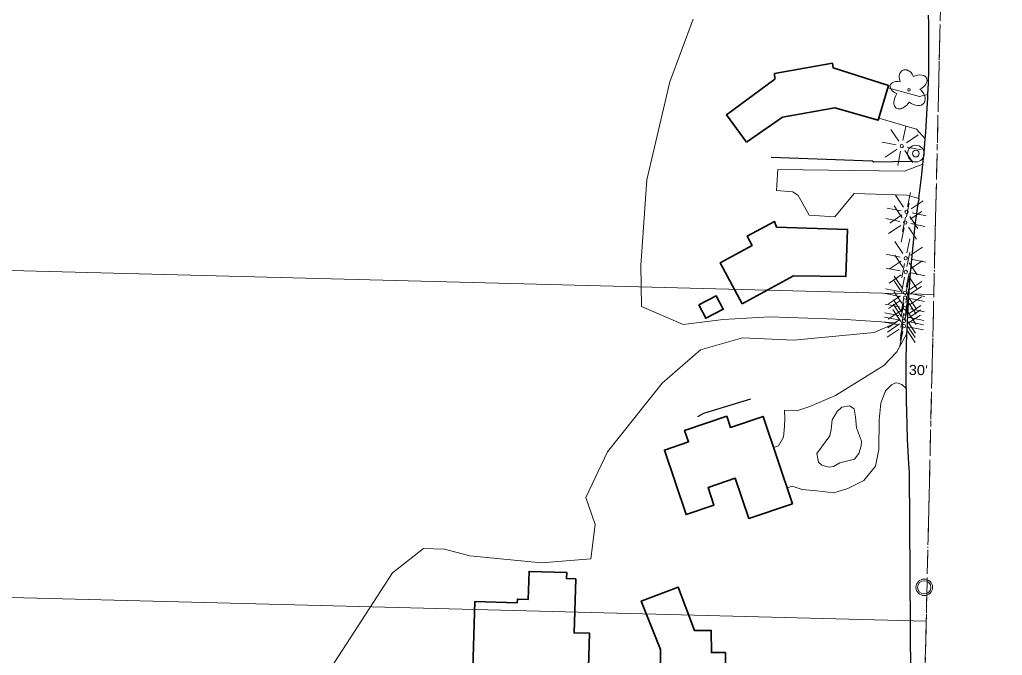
# Model space of a CAD drawing. Extents: x -861682 to -858969, y -1797841 to -1795153.
# Drawn here: x -859566 to -858974, y -1797184 to -1796801 of the extents above; entities that cross this region are included whole.
import ezdxf

# ---------------------------------------------------------------- set-up
doc = ezdxf.new("R2010")
doc.units = 0
doc.header["$LTSCALE"] = 2.4
doc.linetypes.add('DOT_DASHED', pattern=[7.7, 5, -1.2, 0.3, -1.2])
doc.linetypes.add('LONG_DASH_SHORT_DASH', pattern=[9.9, 6, -1.2, 1.5, -1.2])
for name, color, linetype, lineweight in [('10', 7, 'Continuous', 25), ('11', 7, 'Continuous', 13), ('12', 7, 'Continuous', 35), ('14', 7, 'Continuous', 25), ('17', 7, 'Continuous', 13), ('18', 7, 'Continuous', 13), ('30', 7, 'Continuous', 13), ('31', 7, 'Continuous', 13), ('32', 7, 'LONG_DASH_SHORT_DASH', 13), ('36', 7, 'Continuous', 13), ('61', 7, 'Continuous', 13)]:
    doc.layers.add(name, color=color, linetype=linetype, lineweight=lineweight)
doc.layers.add('43', color=7, linetype='Continuous')

msp = doc.modelspace()

# ---------------------------------------------------------------- linework, layer by layer
at = {"layer": '10'}
for p, q in [((-859024.72, -1796908.735), (-859024.961, -1796910.654)), ((-859030.522, -1797073.318), (-859029.495, -1797214.848))]:
    msp.add_line(p, q, dxfattribs=at)
for points in [[(-859019.18, -1796846.215), (-859018.913, -1796839.312), (-859018.708, -1796831.601), (-859018.601, -1796824.99), (-859018.565, -1796820.582), (-859018.557, -1796817.276), (-859018.56, -1796815.072), (-859018.588, -1796810.664), (-859018.695, -1796803.495), (-859018.813, -1796798.497)], [(-859020.84, -1796872.822), (-859020.518, -1796869.02), (-859019.773, -1796858.026), (-859019.254, -1796848.121), (-859019.18, -1796846.215)], [(-859022.275, -1796888.192), (-859021.542, -1796881.099), (-859020.84, -1796872.822)], [(-859024.72, -1796908.735), (-859022.903, -1796894.252), (-859022.275, -1796888.192)], [(-859031.785, -1796989.999), (-859031.739, -1796988.57), (-859031.299, -1796978.662), (-859030.667, -1796967.66), (-859029.621, -1796953.373), (-859028.537, -1796941.3), (-859026.767, -1796924.865), (-859024.961, -1796910.654)], [(-859032.318, -1797023.072), (-859032.326, -1797021.623), (-859032.329, -1797019.419), (-859032.322, -1797016.113), (-859032.292, -1797011.705), (-859032.202, -1797005.094), (-859032.028, -1796997.382), (-859031.785, -1796989.999)], [(-859032.318, -1797023.072), (-859032.31, -1797024.929), (-859032.253, -1797030.439), (-859032.135, -1797037.049), (-859031.929, -1797044.761), (-859031.604, -1797053.571), (-859030.842, -1797068.328), (-859030.522, -1797073.318)]]:
    msp.add_lwpolyline(points, dxfattribs=at)
at = {"layer": '11'}
for points in [[(-859043.287, -1796842.277), (-859024.301, -1796847.432), (-859019.18, -1796846.215)], [(-859048.691, -1796860.39), (-859026.121, -1796867.138), (-859020.84, -1796872.822)], [(-859024.72, -1796908.735), (-859031.775, -1796906.68), (-859063.615, -1796905.802), (-859075.124, -1796919.876), (-859090.539, -1796918.735), (-859097.27, -1796906.978), (-859100.381, -1796904.715), (-859110.27, -1796903.883), (-859109.563, -1796891.373), (-859033.347, -1796892.373), (-859022.275, -1796888.192)], [(-859112.048, -1797058.472), (-859109.015, -1797057.494), (-859106.144, -1797052.254), (-859105.419, -1797045.672), (-859105.324, -1797041.026), (-859105.523, -1797035.979), (-859097.509, -1797036.218), (-859090.292, -1797033.891), (-859074.714, -1797027.204), (-859045.723, -1797009.172), (-859037.895, -1797001.052), (-859031.785, -1796989.999)], [(-859103.872, -1797082.861), (-859100.926, -1797081.857), (-859094.737, -1797083.799), (-859086.084, -1797084.524), (-859075.743, -1797085.798), (-859067.271, -1797083.262), (-859057.704, -1797078.466), (-859050.82, -1797069.651), (-859048.803, -1797059.675), (-859048.531, -1797041.817), (-859047.536, -1797031.874), (-859044.623, -1797024.406), (-859041.126, -1797020.926), (-859038.753, -1797019.638), (-859037.007, -1797019.746), (-859034.862, -1797020.611), (-859032.318, -1797023.072)]]:
    msp.add_lwpolyline(points, dxfattribs=at)
msp.add_lwpolyline([(-859072.261, -1797067.829), (-859063.427, -1797065.633), (-859060.659, -1797062.076), (-859059.386, -1797057.438), (-859059.245, -1797054.643), (-859062.159, -1797046.594), (-859062.835, -1797039.989), (-859063.53, -1797035.23), (-859066.415, -1797033.459), (-859070.928, -1797034.296), (-859073.76, -1797036.83), (-859076.88, -1797041.959), (-859077.393, -1797047.694), (-859078.205, -1797051.563), (-859085.958, -1797062.078), (-859085.003, -1797067.266), (-859082.946, -1797069.05), (-859078.69, -1797070.3), (-859076.084, -1797069.887)], close=True, dxfattribs=at)
at = {"layer": '12'}
for points in [[(-859128.246, -1796874.898), (-859106.732, -1796859.768), (-859075.22, -1796854.136), (-859049.07, -1796861.659), (-859042.826, -1796840.732), (-859076.192, -1796830.117), (-859076.672, -1796827.431), (-859111.402, -1796833.638), (-859111.375, -1796837.026), (-859140.394, -1796858.425)], [(-859130.951, -1796972.06), (-859099.968, -1796955.298), (-859068.521, -1796955.75), (-859067.538, -1796927.473), (-859110.269, -1796925.987), (-859111.495, -1796922.579), (-859127.981, -1796931.496), (-859124.971, -1796937.061), (-859144.243, -1796947.485)], [(-859156.954, -1796972.765), (-859146.489, -1796967.357), (-859142.332, -1796975.402), (-859152.797, -1796980.81)], [(-859100.701, -1797092.323), (-859118.303, -1797039.813), (-859138.005, -1797046.417), (-859140.248, -1797039.725), (-859165.531, -1797048.199), (-859163.182, -1797055.207), (-859177.651, -1797060.057), (-859164.646, -1797098.855), (-859147.873, -1797093.233), (-859151.466, -1797082.514), (-859135.061, -1797077.015), (-859126.977, -1797101.131)], [(-859293.028, -1797191.733), (-859291.802, -1797151.153), (-859266.164, -1797151.928), (-859266.098, -1797149.742), (-859259.591, -1797149.938), (-859259.084, -1797133.096), (-859236.439, -1797133.778), (-859236.547, -1797137.368), (-859230.999, -1797137.535), (-859231.977, -1797170.014), (-859222.695, -1797170.294), (-859223.313, -1797190.787), (-859227.899, -1797190.649), (-859228.677, -1797216.497), (-859258.24, -1797215.607), (-859257.554, -1797192.801)], [(-859188.067, -1797239.176), (-859188.171, -1797214.698), (-859212.563, -1797214.801), (-859212.607, -1797204.4), (-859191.694, -1797204.312), (-859191.671, -1797209.768), (-859179.866, -1797209.719), (-859179.991, -1797179.954), (-859191.675, -1797150.887), (-859169.429, -1797142.508), (-859159.61, -1797168.611), (-859149.486, -1797168.569), (-859149.43, -1797181.911), (-859141.05, -1797181.876), (-859140.905, -1797216.333), (-859153.003, -1797216.384), (-859153.037, -1797208.389), (-859165.952, -1797208.444), (-859165.098, -1797238.609)]]:
    msp.add_lwpolyline(points, close=True, dxfattribs=at)
at = {"layer": '14'}
for points in [[(-859028.47, -1796886.438), (-859051.691, -1796886.855), (-859052.743, -1796886.344), (-859113.392, -1796884.009)], [(-859157.508, -1797039.963), (-859154.038, -1797037.947), (-859125.659, -1797029.308)]]:
    msp.add_lwpolyline(points, dxfattribs=at)
at = {"layer": '17'}
for p, q in [((-859036.757, -1796874.325), (-859041.547, -1796867.197)), ((-859034.297, -1796873.865), (-859032.571, -1796865.465)), ((-859032.097, -1796875.265), (-859025.001, -1796870.525)), ((-859038.257, -1796876.525), (-859046.719, -1796874.851)), ((-859037.717, -1796879.025), (-859044.943, -1796883.881)), ((-859031.657, -1796877.785), (-859023.177, -1796879.509)), ((-859037.337, -1796888.985), (-859035.657, -1796880.385)), ((-859032.997, -1796879.925), (-859028.197, -1796887.139)), ((-859033.846, -1796913.95), (-859038.636, -1796906.822)), ((-859031.386, -1796913.49), (-859029.66, -1796905.09)), ((-859035.346, -1796916.15), (-859043.808, -1796914.476)), ((-859034.622, -1796920.338), (-859039.412, -1796913.21)), ((-859032.162, -1796919.878), (-859030.436, -1796911.478)), ((-859029.186, -1796914.89), (-859022.09, -1796910.15)), ((-859034.806, -1796918.65), (-859042.032, -1796923.506)), ((-859034.426, -1796928.61), (-859032.746, -1796920.01)), ((-859030.086, -1796919.55), (-859025.286, -1796926.764)), ((-859029.962, -1796921.278), (-859022.866, -1796916.538)), ((-859028.746, -1796917.41), (-859020.266, -1796919.134)), ((-859036.122, -1796922.538), (-859044.584, -1796920.864)), ((-859035.582, -1796925.038), (-859042.808, -1796929.894)), ((-859035.202, -1796934.998), (-859033.522, -1796926.398)), ((-859030.862, -1796925.938), (-859026.062, -1796933.152)), ((-859029.522, -1796923.798), (-859021.042, -1796925.522)), ((-859034.291, -1796941.803), (-859039.081, -1796934.675)), ((-859031.831, -1796941.343), (-859030.105, -1796932.943)), ((-859029.631, -1796942.743), (-859022.535, -1796938.003)), ((-859035.791, -1796944.003), (-859044.253, -1796942.329)), ((-859034.353, -1796950.052), (-859039.143, -1796942.924)), ((-859031.893, -1796949.592), (-859030.167, -1796941.192)), ((-859035.251, -1796946.503), (-859042.477, -1796951.359)), ((-859034.871, -1796956.463), (-859033.191, -1796947.863)), ((-859030.531, -1796947.403), (-859025.731, -1796954.617)), ((-859029.693, -1796950.992), (-859022.597, -1796946.252)), ((-859029.191, -1796945.263), (-859020.711, -1796946.987)), ((-859035.853, -1796952.252), (-859044.315, -1796950.578)), ((-859035.313, -1796954.752), (-859042.539, -1796959.608)), ((-859034.707, -1796962.52), (-859039.497, -1796955.392)), ((-859032.247, -1796962.06), (-859030.521, -1796953.66)), ((-859030.593, -1796955.652), (-859025.793, -1796962.866)), ((-859029.253, -1796953.512), (-859020.773, -1796955.236)), ((-859034.76, -1796965.448), (-859039.55, -1796958.32)), ((-859034.933, -1796964.712), (-859033.253, -1796956.112)), ((-859032.3, -1796964.988), (-859030.574, -1796956.588)), ((-859030.1, -1796966.388), (-859023.004, -1796961.648)), ((-859030.047, -1796963.46), (-859022.951, -1796958.72)), ((-859036.26, -1796967.648), (-859044.722, -1796965.974)), ((-859036.207, -1796964.72), (-859044.669, -1796963.046)), ((-859035.667, -1796967.22), (-859042.893, -1796972.076)), ((-859034.862, -1796971.75), (-859039.652, -1796964.622)), ((-859032.402, -1796971.29), (-859030.676, -1796962.89)), ((-859029.607, -1796965.98), (-859021.127, -1796967.704)), ((-859036.362, -1796973.95), (-859044.824, -1796972.276)), ((-859035.72, -1796970.148), (-859042.946, -1796975.004)), ((-859035.341, -1796979.527), (-859040.131, -1796972.399)), ((-859035.181, -1796976.924), (-859039.971, -1796969.796)), ((-859035.34, -1796980.108), (-859033.66, -1796971.508)), ((-859035.287, -1796977.18), (-859033.607, -1796968.58)), ((-859033.009, -1796982.181), (-859031.283, -1796973.781)), ((-859032.881, -1796979.067), (-859031.155, -1796970.667)), ((-859032.721, -1796976.464), (-859030.995, -1796968.064)), ((-859031, -1796971.048), (-859026.2, -1796978.262)), ((-859030.947, -1796968.12), (-859026.147, -1796975.334)), ((-859030.521, -1796977.864), (-859023.425, -1796973.124)), ((-859030.202, -1796972.69), (-859023.106, -1796967.95)), ((-859029.66, -1796968.908), (-859021.18, -1796970.632)), ((-859036.681, -1796979.124), (-859045.143, -1796977.45)), ((-859035.822, -1796976.45), (-859043.048, -1796981.306)), ((-859035.469, -1796982.641), (-859040.259, -1796975.513)), ((-859035.442, -1796986.41), (-859033.762, -1796977.81)), ((-859031.102, -1796977.35), (-859026.302, -1796984.564)), ((-859030.809, -1796983.581), (-859023.713, -1796978.841)), ((-859030.681, -1796980.467), (-859023.585, -1796975.727)), ((-859029.762, -1796975.21), (-859021.282, -1796976.934)), ((-859036.969, -1796984.841), (-859045.431, -1796983.167)), ((-859036.841, -1796981.727), (-859045.303, -1796980.053)), ((-859036.301, -1796984.227), (-859043.527, -1796989.083)), ((-859036.141, -1796981.624), (-859043.367, -1796986.48)), ((-859035.921, -1796994.187), (-859034.241, -1796985.587)), ((-859035.761, -1796991.584), (-859034.081, -1796982.984)), ((-859031.581, -1796985.127), (-859026.781, -1796992.341)), ((-859031.421, -1796982.524), (-859026.621, -1796989.738)), ((-859030.241, -1796982.987), (-859021.761, -1796984.711)), ((-859030.081, -1796980.384), (-859021.601, -1796982.108)), ((-859036.429, -1796987.341), (-859043.655, -1796992.197)), ((-859036.049, -1796997.301), (-859034.369, -1796988.701)), ((-859031.709, -1796988.241), (-859026.909, -1796995.455)), ((-859030.369, -1796986.101), (-859021.889, -1796987.825))]:
    msp.add_line(p, q, dxfattribs=at)
msp.add_lwpolyline([(-859030.411, -1796850.791), (-859029.369, -1796851.559), (-859027.963, -1796852.281), (-859026.715, -1796852.687), (-859025.343, -1796852.883), (-859024.325, -1796852.833), (-859023.181, -1796852.543), (-859022.249, -1796851.991), (-859021.509, -1796851.203), (-859021.041, -1796850.245), (-859020.831, -1796849.167), (-859020.935, -1796847.971), (-859021.225, -1796846.799), (-859021.711, -1796845.739), (-859022.433, -1796844.595), (-859023.299, -1796843.675), (-859023.981, -1796843.063), (-859022.799, -1796842.347), (-859021.653, -1796841.399), (-859020.733, -1796840.307), (-859020.211, -1796839.451), (-859019.879, -1796838.637), (-859019.733, -1796837.821), (-859019.773, -1796837.059), (-859019.989, -1796836.379), (-859020.247, -1796835.927), (-859020.667, -1796835.453), (-859021.127, -1796835.099), (-859021.693, -1796834.809), (-859022.929, -1796834.481), (-859024.171, -1796834.447), (-859026.217, -1796834.823), (-859027.877, -1796835.461), (-859028.667, -1796833.883), (-859029.321, -1796833.069), (-859029.733, -1796832.667), (-859030.197, -1796832.267), (-859030.799, -1796831.875), (-859031.803, -1796831.443), (-859032.817, -1796831.273), (-859033.705, -1796831.373), (-859034.505, -1796831.707), (-859035.171, -1796832.193), (-859035.731, -1796832.899), (-859036.081, -1796833.655), (-859036.239, -1796834.093), (-859036.407, -1796834.769), (-859036.459, -1796835.931), (-859036.387, -1796836.829), (-859036.175, -1796837.791), (-859035.891, -1796838.597), (-859037.333, -1796838.365), (-859038.691, -1796838.415), (-859039.849, -1796838.701), (-859040.737, -1796839.199), (-859041.177, -1796839.543), (-859041.611, -1796840.109), (-859041.849, -1796840.643), (-859041.973, -1796841.321), (-859041.771, -1796842.425), (-859041.315, -1796843.237), (-859040.691, -1796843.999), (-859039.913, -1796844.615), (-859039.215, -1796845.039), (-859038.551, -1796845.327), (-859037.823, -1796845.565), (-859038.507, -1796846.777), (-859039.129, -1796848.145), (-859039.525, -1796849.647), (-859039.659, -1796850.981), (-859039.649, -1796852.071), (-859039.315, -1796853.089), (-859038.793, -1796853.935), (-859038.235, -1796854.371), (-859037.849, -1796854.617), (-859037.115, -1796854.841), (-859036.321, -1796854.853), (-859035.551, -1796854.729), (-859034.891, -1796854.517), (-859034.147, -1796854.195), (-859033.071, -1796853.515), (-859032.109, -1796852.729), (-859031.153, -1796851.711), (-859030.407, -1796850.801)], dxfattribs=at)
for centre, radius in [((-859030.591, -1796843.379), 0.773), ((-859034.957, -1796877.225), 1), ((-859032.046, -1796916.85), 1), ((-859032.822, -1796923.238), 1), ((-859032.491, -1796944.703), 1), ((-859032.553, -1796952.952), 1), ((-859032.96, -1796968.348), 1), ((-859032.907, -1796965.42), 1), ((-859033.062, -1796974.65), 1), ((-859033.381, -1796979.824), 1), ((-859033.669, -1796985.541), 1), ((-859033.541, -1796982.427), 1)]:
    msp.add_circle(centre, radius, dxfattribs=at)
at = {"layer": '18'}
msp.add_lwpolyline([(-859385.245, -1797201.598), (-859341.309, -1797133.89), (-859322.661, -1797119.267), (-859309.907, -1797119.639), (-859294.706, -1797123.73), (-859251.594, -1797127.82), (-859221.915, -1797125.507), (-859219.271, -1797104.832), (-859224.872, -1797088.684), (-859211.894, -1797061.126), (-859178.991, -1797019.917), (-859156.053, -1796999.792), (-859130.756, -1796992.589), (-859099.874, -1796994.014), (-859051.539, -1796989.345), (-859038.372, -1796983.529), (-859068.61, -1796981.475), (-859114.201, -1796979.876), (-859142.274, -1796981.46), (-859166.334, -1796984.629), (-859191.529, -1796973.646), (-859191.8, -1796949.095), (-859188.271, -1796897.505), (-859174.444, -1796838.584), (-859160.301, -1796800.902)], dxfattribs=at)
at = {"layer": '30'}
for p, q in [((-859015.656, -1796966.547), (-859737.749, -1796947.769)), ((-859020.232, -1797163.052), (-859830.702, -1797141.975))]:
    msp.add_line(p, q, dxfattribs=at)
at = {"layer": '31'}
for radius in [5, 2]:
    msp.add_circle((-859026.438, -1796881.752), radius, dxfattribs=at)
at = {"layer": '32'}
msp.add_line((-859002.083, -1796383.657), (-859035.9, -1797835.881), dxfattribs=at)
at = {"layer": '36'}
for radius in [5, 4]:
    msp.add_circle((-859021.4, -1797142.633), radius, dxfattribs=at)
at = {"layer": '61', "linetype": 'DOT_DASHED'}
msp.add_line((-859035.9, -1797835.881), (-858974.429, -1795196.105), dxfattribs=at)

# ---------------------------------------------------------------- texts
at = {"layer": '43', "width": 1.1}
msp.add_text("30'", height=6, rotation=358.688, dxfattribs=at).set_placement((-859030.829, -1797014.795))

doc.saveas('drawing.dxf')
